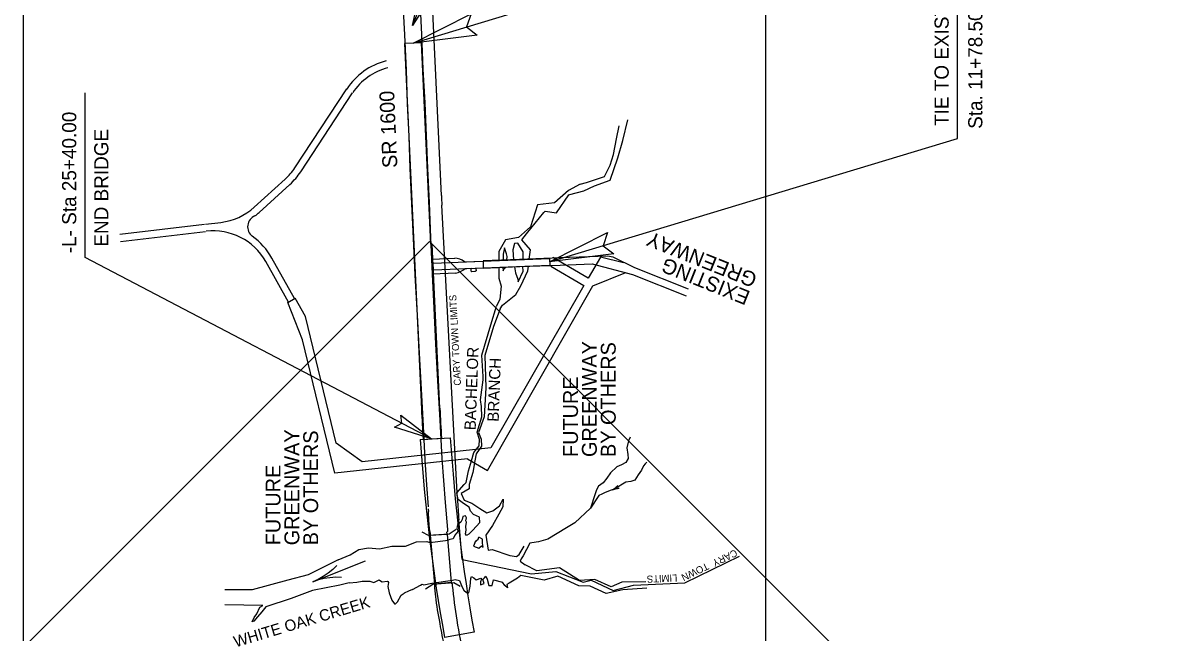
# Model space of a CAD drawing. Extents: x 2026893 to 2039781, y 729195 to 739590.
# Drawn here: x 2028294 to 2029929, y 737234 to 738095 of the extents above; entities that cross this region are included whole.
import ezdxf

# ---------------------------------------------------------------- set-up
doc = ezdxf.new("R2010")
doc.units = 0
for name, color, linetype in [('Default', 7, 'Continuous'), ('Old_Level_1', 7, 'Continuous'), ('Old_Level_11', 7, 'Continuous'), ('Old_Level_2', 7, 'Continuous'), ('Old_Level_20', 7, 'Continuous'), ('Old_Level_22', 7, 'Continuous'), ('Old_Level_3', 7, 'Continuous'), ('Prop Conc 5in Monolithic Keyed In Island', 7, 'Continuous'), ('Prop EOT Dash', 7, 'Continuous'), ('Prop Shade Heavy', 7, 'Continuous'), ('Prop Shade Light', 7, 'Continuous'), ('Prop Terminator CELL', 7, 'Continuous')]:
    doc.layers.add(name, color=color, linetype=linetype)

# ---------------------------------------------------------------- blocks, each defined once
blk = doc.blocks.new('EXIST HYDRO RIVER FLOW ARROW')
at = {"layer": 'Default'}
for p, q in [((0.2, 0), (-0.2, 0)), ((0, 0.04575), (0.03775, 0.03)), ((0, 0), (0, 0)), ((0.03775, 0.03), (0.07725, 0.01725)), ((0.07725, 0.01725), (0.118, 0.00775)), ((0.118, 0.00775), (0.159, 0.0015)), ((0.159, 0.0015), (0.2, 0)), ((0.159, -0.0015), (0.2, 0)), ((0, -0.04575), (0.03775, -0.03)), ((0.03775, -0.03), (0.07725, -0.01725)), ((0.07725, -0.01725), (0.118, -0.00775)), ((0.118, -0.00775), (0.159, -0.0015))]:
    blk.add_line(p, q, dxfattribs=at)
blk = doc.blocks.new('EXIST HYDRO STREAM FLOW ARROW')
at = {"layer": 'Default'}
blk.add_line((0, 0), (0, 0), dxfattribs=at)
for points in [[(-0.1, 0.04575), (-0.07325, 0.03375), (-0.04475, 0.0245), (-0.0165, 0.01575), (0.01175, 0.0095), (0.041, 0.00475), (0.07075, 0.0015), (0.1, 0)], [(-0.1, -0.04575), (-0.07325, -0.03375), (-0.04475, -0.0245), (-0.0165, -0.01575), (0.01175, -0.0095), (0.041, -0.00475), (0.07075, -0.0015), (0.1, 0)]]:
    blk.add_lwpolyline(points, dxfattribs=at)

msp = doc.modelspace()

# ---------------------------------------------------------------- linework, layer by layer
at = {"layer": 'Default'}
for p, q in [((2028885.6, 737851.8), (2028860.8, 738391.3)), ((2028908.3, 737422.7), (2028886.3, 737838.2)), ((2028872.2, 737762.1), (2028904.4, 737763.2)), ((2028915, 737337.3), (2028910.3, 737393.6)), ((2028915, 737337.3), (2029012.9, 737317.4)), ((2029229.7, 737304.3), (2029307, 737342)), ((2029012.9, 737317.4), (2029047.5, 737320.7)), ((2029047.5, 737320.7), (2029086.1, 737305.5)), ((2029086.1, 737305.5), (2029097.3, 737308.2)), ((2029097.3, 737308.2), (2029128.4, 737293.8)), ((2029157.1, 737301.1), (2029229.7, 737304.3)), ((2029128.4, 737293.8), (2029157.1, 737301.1))]:
    msp.add_line(p, q, dxfattribs=at)
for points in [[(2028906, 737742.2), (2028873.2, 737740.5), (2028872.2, 737762.1)], [(2029053.3, 737763.6), (2028995.9, 737761.3), (2028944.6, 737759.3)], [(2029234.7, 737719.4), (2029159.1, 737749.5), (2029128.4, 737764.5), (2029120.6, 737766.3), (2029053.3, 737763.6)], [(2028918.2, 737758.2), (2028944.6, 737759.2), (2028944.9, 737749.3), (2028934.4, 737748.8), (2028934.6, 737745.3), (2028933.6, 737744.3), (2028928.7, 737744.2), (2028927.6, 737745.1), (2028927.5, 737748.6), (2028918.9, 737748.2)], [(2028944.9, 737749.3), (2028996.3, 737751.3), (2029053.3, 737753.6)], [(2029053.3, 737753.6), (2029098.8, 737755.5), (2029155.7, 737740.3), (2029231.5, 737709.9)]]:
    msp.add_lwpolyline(points, dxfattribs=at)
for centre, radius, start, end in [((2030853.6, 737942.3), 1970, 182.6308, 183.0286), ((2029876.9, 737474), 970, 183.0286, 184.7504)]:
    msp.add_arc(centre, radius, start, end, dxfattribs=at)
for centre, major_axis, ratio, start_param, end_param in [((2028904.1, 737740.8), (19.8, 10.5), 0.999895, 0.400767, 1.068838), ((2028899.8, 737772.6), (-23.2, -20.5), 0.998646, 1.047139, 1.510472)]:
    msp.add_ellipse(centre, major_axis=major_axis, ratio=ratio, start_param=start_param, end_param=end_param, dxfattribs=at)
at = {"layer": 'Old_Level_1'}
for p, q in [((2028844.6, 738092.3), (2029101.4, 738704.5)), ((2029615.3, 737932.6), (2029615.3, 738285.3)), ((2028845.7, 738067.3), (2029426.2, 738243.1)), ((2028381.9, 737764.1), (2028381.9, 737996.9)), ((2029038.6, 737758), (2029615.3, 737932.6)), ((2028871.8, 737507.9), (2028381.9, 737764.1))]:
    msp.add_line(p, q, dxfattribs=at)
at = {"layer": 'Old_Level_11'}
for p, q in [((2029142.1, 737929.7), (2029149.1, 737958.6)), ((2029133.2, 737931.8), (2029136.7, 737950.3)), ((2029129, 737910), (2029133.2, 737931.8)), ((2029135, 737905), (2029142.1, 737929.7)), ((2029124.1, 737894.9), (2029129, 737910)), ((2029116.3, 737878.6), (2029124.1, 737894.9)), ((2029124.2, 737873.7), (2029135, 737905)), ((2028972.6, 737750.4), (2028972.9, 737745.3)), ((2029103, 737430.2), (2029096.4, 737410.2))]:
    msp.add_line(p, q, dxfattribs=at)
for points in [[(2029081.7, 737868), (2029090.9, 737870.2), (2029116.3, 737878.6)], [(2029081.7, 737868), (2029065.1, 737859.1), (2029045.3, 737841.5), (2029021.3, 737838.6), (2029011.6, 737807.4), (2028994.6, 737792.7), (2028976.2, 737789.2), (2028966.8, 737772.9), (2028966.7, 737760.2)], [(2029087.1, 737858.6), (2029102, 737865.5), (2029124.2, 737873.7)], [(2029009.9, 737761.9), (2029011.4, 737774.9), (2028999.3, 737789.1), (2029006.1, 737797.6), (2029030.3, 737827.9), (2029032.3, 737829.7), (2029048.4, 737827.6), (2029066, 737852.8), (2029067.1, 737853.4), (2029087.1, 737858.6)], [(2028978.3, 737760.6), (2028978.6, 737765.7), (2028977.5, 737769.5), (2028974.6, 737778.1), (2028972.9, 737769.1), (2028972.9, 737760.4)], [(2029001.1, 737761.5), (2029001.1, 737772.2), (2028993.5, 737784.5), (2028989.2, 737784.1), (2028986.4, 737775.1), (2028987.6, 737761)], [(2028966.7, 737750.1), (2028966.6, 737734.8), (2028970, 737723.6), (2028968.1, 737705.4), (2028963.6, 737695.5)], [(2028968.5, 737691.5), (2028971.9, 737697), (2028990.9, 737711.8), (2028998, 737724.2), (2029008, 737745.3), (2029008.8, 737751.8)], [(2028972.9, 737745.3), (2028974.5, 737748.9), (2028976.5, 737750.5)], [(2028989, 737751), (2028990.5, 737742.4), (2028993.7, 737733.8), (2028994, 737729.9), (2029001, 737744.9), (2029000.9, 737751.5)], [(2028936, 737517.2), (2028942.9, 737539.2), (2028942.1, 737553.6), (2028941, 737562.9), (2028944.5, 737591.2), (2028944.5, 737596.3), (2028943, 737626.4), (2028955.4, 737669.2), (2028963.6, 737695.5)], [(2028968.5, 737691.5), (2028959.1, 737666.6), (2028947.1, 737625.9), (2028948.4, 737580.2), (2028946.1, 737538.9), (2028938.3, 737516.8)], [(2028907.3, 737431.5), (2028917.6, 737443.6), (2028920.6, 737446.1), (2028923.9, 737462.7), (2028928.3, 737476.9), (2028931.5, 737488.6), (2028939.1, 737498), (2028939.7, 737506.9), (2028936, 737517.2)], [(2028938.3, 737516.8), (2028941.8, 737507.5), (2028942.1, 737497.4), (2028934.7, 737486.9), (2028932.9, 737476.7), (2028930, 737460.5), (2028925.1, 737443.5), (2028924.9, 737437.2), (2028913.7, 737430.9), (2028918, 737421.5), (2028928.8, 737417.1), (2028940.1, 737409.4), (2028949.9, 737403.5), (2028958.5, 737406.1), (2028967.8, 737413.4), (2028972.9, 737422.7), (2028972.5, 737411.9), (2028966.7, 737401.3), (2028957.8, 737385.3), (2028948.3, 737371.7), (2028951.6, 737350.7)], [(2029152.3, 737510.2), (2029152.3, 737510.2), (2029149.9, 737505.2), (2029147.8, 737495.3), (2029149.1, 737485.8), (2029149.5, 737480.1), (2029146.3, 737474.3), (2029140, 737471.2), (2029133.4, 737468.4), (2029124.6, 737460), (2029119.5, 737452.2), (2029114.2, 737445.6), (2029107.6, 737440.9), (2029105, 737436.1), (2029103, 737430.2)], [(2029176.2, 737474.9), (2029173.6, 737472.7), (2029171.4, 737469.9), (2029168.5, 737463.8), (2029163.9, 737457.3), (2029159.2, 737449.4), (2029153.5, 737447.8), (2029146.4, 737446.9), (2029139.2, 737442.5), (2029132.3, 737438), (2029124.2, 737434.8), (2029116.2, 737431.8), (2029112.4, 737429.7), (2029108.4, 737428)], [(2028909.2, 737422.1), (2028907.3, 737431.5)], [(2028939.9, 737389.6), (2028939.7, 737397.5), (2028931.1, 737401.1), (2028926.7, 737405.8), (2028925.1, 737411.5), (2028916.9, 737416.7), (2028909.2, 737422.1)], [(2029108.4, 737428), (2029096.4, 737410.2), (2029074.1, 737389.1), (2029062.3, 737382.2)], [(2028939.9, 737389.6), (2028929.9, 737378.7), (2028924.4, 737373.3), (2028921.2, 737371.3), (2028919.9, 737373.5), (2028920.8, 737379.1), (2028920.1, 737384.3), (2028921.3, 737390.3), (2028920, 737392.3), (2028921.2, 737396.3), (2028919.6, 737399.2), (2028915.9, 737398.1), (2028914.8, 737394.1), (2028912.9, 737390), (2028908.6, 737387.1), (2028907.4, 737381.3), (2028909.5, 737377.5), (2028904.6, 737372), (2028902.2, 737366.6), (2028897.4, 737365.9), (2028895.3, 737364.8)], [(2028935.3, 737364.5), (2028937.4, 737366.2), (2028938.7, 737369)], [(2028943.6, 737360.7), (2028943.5, 737366.4), (2028938.7, 737369)], [(2029062.3, 737382.2), (2029035.9, 737366.4), (2029022.7, 737362.5), (2029019.8, 737361.9), (2029010.5, 737360.7), (2029001.1, 737342.8)], [(2028739.8, 737336.9), (2028756.8, 737344.2), (2028768.9, 737351.8), (2028782.7, 737353.9), (2028798, 737352.7), (2028815.5, 737356.1), (2028834.9, 737356.5), (2028850.5, 737362.3), (2028865, 737363.1), (2028869.2, 737361.5), (2028895.3, 737364.8)], [(2028933.1, 737360.8), (2028931.2, 737356.4), (2028938.6, 737353.6), (2028942.1, 737356.6), (2028944.6, 737354.7)], [(2028933.1, 737360.8), (2028935.3, 737364.5)], [(2028944.6, 737354.7), (2028943.6, 737360.7)], [(2028995.4, 737344.6), (2029002.4, 737356.5)], [(2028739.8, 737336.9), (2028697.2, 737316), (2028668.4, 737308.4), (2028618.1, 737294.8), (2028579.3, 737294.5)], [(2028951.6, 737350.7), (2028957.6, 737351.4)], [(2028957.6, 737351.4), (2028982.6, 737343.1), (2028991.6, 737341.8), (2028995.4, 737344.6)], [(2029001.1, 737342.8), (2028998.6, 737338.6), (2028997.1, 737335.1), (2029004.1, 737329.9)], [(2029020.4, 737321.3), (2029004.1, 737329.9)], [(2029174.4, 737306.1), (2029140.9, 737305.3), (2029125.5, 737298.6), (2029102.5, 737309.4), (2029081, 737307.8), (2029052.4, 737325.7), (2029020.4, 737321.3)], [(2028755.1, 737304.3), (2028742, 737301.2), (2028703.6, 737293.8), (2028673.4, 737282.3), (2028637.6, 737270.6), (2028631.7, 737263.7), (2028625.5, 737256.2), (2028620.6, 737250.4), (2028618, 737249.4), (2028621.2, 737255.7), (2028624.7, 737260.6), (2028628.9, 737270.2), (2028633.3, 737272.3), (2028579.6, 737273.2)], [(2028755.1, 737304.3), (2028766.3, 737305.4), (2028773.5, 737307), (2028784.3, 737306.8), (2028790.1, 737304.9), (2028797.6, 737308.9), (2028799.7, 737307.5), (2028802, 737306.1), (2028808.8, 737306.7), (2028810.1, 737306.4), (2028810.8, 737305.1), (2028809.8, 737299.5), (2028811.7, 737290.4)], [(2028845, 737295), (2028856.1, 737301.2), (2028858.4, 737302.4), (2028860.8, 737301.8), (2028872, 737304.2), (2028901.1, 737308.2)], [(2028901.1, 737308.2), (2028905.1, 737309.1), (2028911.1, 737307.6), (2028914.9, 737298.4), (2028917.5, 737293.9), (2028920.9, 737290.8), (2028924.5, 737290.3), (2028926.2, 737299.9), (2028927.2, 737310.7), (2028928, 737313.2), (2028931.3, 737311.5), (2028934.7, 737308.7), (2028941.3, 737311.1), (2028942.4, 737309.5), (2028941, 737306), (2028941, 737301.5), (2028945.9, 737303.5), (2028944.3, 737309.4), (2028946.7, 737311.7), (2028948.6, 737314)], [(2028948.6, 737314), (2028950.5, 737309.5)], [(2028950.5, 737309.5), (2028952.9, 737300.7), (2028956.9, 737300.7), (2028957.4, 737300.9), (2028959.2, 737308.9), (2028972.1, 737305.2)], [(2028993.1, 737311.1), (2028981.5, 737304.2), (2028977.9, 737302), (2028979, 737297.5), (2028975.3, 737300.7), (2028972.1, 737305.2)], [(2028997.7, 737314.7), (2028993.1, 737311.1)], [(2029175.8, 737297), (2029142, 737294.5), (2029118.7, 737289.3), (2029095.9, 737299.8), (2029079.8, 737300), (2029050.1, 737314), (2029031, 737308), (2028997.7, 737314.7)], [(2028811.7, 737290.4), (2028815.7, 737279.9), (2028819.2, 737274.9), (2028820.7, 737275), (2028823.6, 737277.7), (2028828.6, 737287.1), (2028832.8, 737289.9)], [(2028845, 737295), (2028839, 737292.5), (2028832.8, 737289.9)]]:
    msp.add_lwpolyline(points, dxfattribs=at)
at = {"layer": 'Old_Level_20'}
for p, q in [((2028868.8, 737786.8), (2028294.4, 737212.4)), ((2029344.4, 737311.2), (2028868.8, 737786.8))]:
    msp.add_line(p, q, dxfattribs=at)
at = {"layer": 'Old_Level_22'}
for p, q in [((2028294.4, 738629.8), (2028294.4, 737129.7)), ((2029344.4, 737129.7), (2029344.4, 738629.7)), ((2028857.7, 738067.8), (2028833.7, 738066.7)), ((2028833.7, 738066.7), (2028857.5, 737549.9)), ((2028870.8, 737783.1), (2028857.7, 738067.8)), ((2028872.8, 737783.2), (2028870.8, 737783.1)), ((2028883.4, 737551.1), (2028872.8, 737783.2)), ((2028859.8, 737507.1), (2028885.8, 737508.8)), ((2029929.5, 736726.1), (2029344.4, 737311.2))]:
    msp.add_line(p, q, dxfattribs=at)
for radius in [2412, 2386]:
    msp.add_arc((2031266.9, 737660.6), radius, 182.6308, 183.6478, dxfattribs=at)
at = {"layer": 'Old_Level_3'}
msp.add_line((2028867, 737409), (2028867.2, 737405.4), dxfattribs=at)
for points in [[(2028891.4, 737417.9), (2028886.9, 737480.2), (2028883.8, 737534.3), (2028880.8, 737589.8), (2028877.9, 737642.4), (2028875.3, 737692.7), (2028873, 737740.5), (2028870.7, 737792.7), (2028868.6, 737841.5), (2028866.5, 737889.9), (2028862.6, 737982.7), (2028860.1, 738030.3), (2028858, 738079.6), (2028855.7, 738128.3), (2028853.7, 738176), (2028851, 738227.2), (2028849, 738276.4), (2028846.7, 738325.3), (2028845.4, 738355.3)], [(2028819.7, 738339.7), (2028823.3, 738286.5), (2028825.8, 738237.2), (2028828.4, 738187.7), (2028830.3, 738140.3), (2028833.4, 738078.8), (2028835.7, 738029.1), (2028837.3, 737981.2), (2028839.4, 737935.7), (2028841.2, 737889.8), (2028843.4, 737840.1), (2028845.7, 737790.9), (2028848.1, 737739.3), (2028851.5, 737682.8), (2028854.1, 737628.7), (2028856.9, 737578.1), (2028859.8, 737526), (2028862.4, 737478.4), (2028864.4, 737442.8), (2028866.7, 737411.7)], [(2028893.7, 737373.9), (2028893.5, 737375.9), (2028894.7, 737377.3), (2028894.7, 737379.9), (2028891.4, 737417.9)], [(2028858.1, 737376.5), (2028867.1, 737371.9), (2028896.8, 737373.7), (2028906.7, 737380.1)], [(2028868.3, 737383.5), (2028868.4, 737380.7), (2028869.8, 737374), (2028869.9, 737372.5)], [(2028869.9, 737371.9), (2028893.9, 737373.4), (2028899.6, 737305), (2028875.7, 737302.7)], [(2028869.9, 737371.9), (2028875.7, 737302.7)], [(2028863.2, 737296.1), (2028873.4, 737302.6), (2028903, 737305), (2028912.3, 737299.7)], [(2028901.5, 737300.9), (2028901.4, 737302.9), (2028899.9, 737303.4), (2028899.8, 737304.5)], [(2028875.9, 737302.5), (2028876, 737297.4)]]:
    msp.add_lwpolyline(points, dxfattribs=at)
msp.add_ellipse((2028579.1, 737379.7), major_axis=(-9.9, 295.3), ratio=0.97889, start_param=4.692284, end_param=4.766746, dxfattribs=at)
for points in [[(2028876, 737297.4), (2028877.7, 737280.7), (2028884.1, 737242.4), (2028890.4, 737209.5), (2028897.8, 737176.1), (2028905.3, 737145.9), (2028914.1, 737113.4), (2028927.8, 737062.5), (2028942.5, 737009), (2028956.7, 736958.8), (2028970.6, 736908.1), (2028981.4, 736866.4), (2028994.6, 736816.4), (2029007.2, 736768.1), (2029020.4, 736717.4), (2029030.8, 736675.2)], [(2028959.3, 737040.6), (2028944.8, 737094.7), (2028931, 737147.5), (2028918.6, 737198.8), (2028907.8, 737251.5), (2028901.5, 737300.9)]]:
    msp.add_spline(points, degree=3, dxfattribs=at)
at = {"layer": 'Prop Conc 5in Monolithic Keyed In Island'}
msp.add_lwpolyline([(2028874.4, 737746.3), (2028874, 737756.3), (2029038.4, 737763), (2029038.8, 737753)], close=True, dxfattribs=at)
at = {"layer": 'Prop EOT Dash'}
for p, q in [((2029093.1, 737735.1), (2029043.3, 737764.2)), ((2029110.5, 737764.9), (2029093.1, 737735.1)), ((2029143, 737756.5), (2029110.5, 737764.9)), ((2029040.2, 737752), (2029087, 737724.7)), ((2029099.9, 737724), (2029146.2, 737743)), ((2028951, 737463.2), (2029099.9, 737724)), ((2029087, 737724.7), (2028955.4, 737495.2)), ((2028668.6, 737700.8), (2028679.1, 737706.6)), ((2028689.3, 737647.8), (2028668.6, 737700.8)), ((2028693.6, 737680.9), (2028679.1, 737706.6)), ((2028736.9, 737501.7), (2028693.6, 737680.9)), ((2028734.8, 737459.3), (2028689.3, 737647.8)), ((2028773.8, 737475.6), (2028736.9, 737501.7)), ((2028955.4, 737495.2), (2028773.8, 737475.6)), ((2028922.3, 737479.6), (2028734.8, 737459.3)), ((2028922.3, 737479.6), (2028951, 737463.2))]:
    msp.add_line(p, q, dxfattribs=at)
for points in [[(2028678.5, 737891), (2028751.9, 738002.4)], [(2028686.8, 737885.5), (2028760.2, 737996.9)], [(2028621.2, 737835.4), (2028664.7, 737874.9)], [(2028627.9, 737828), (2028671.4, 737867.5)], [(2028430.9, 737797), (2028551, 737811.2)], [(2028552, 737811.3), (2028574, 737813.9)], [(2028432.1, 737787), (2028552.2, 737801.2)], [(2028678.2, 737706.2), (2028646, 737763.5)], [(2028669.5, 737701.3), (2028637.3, 737758.6)]]:
    msp.add_lwpolyline(points, dxfattribs=at)
for centre, radius, start, end in [((2028831.2, 737950.1), 95, 104.526, 146.6179), ((2028831.2, 737950.1), 85, 104.526, 146.6179), ((2028607.5, 737937.8), 85, 312.2527, 326.6179), ((2028607.5, 737937.8), 95, 312.2527, 326.6179), ((2028564, 737898.3), 85, 276.74, 312.2527), ((2028564, 737898.3), 95, 307.6996, 312.2527), ((2028628.5, 737807.6), 16.8, 112.2241, 232.4804), ((2028563.2, 737716.9), 85, 29.3209, 96.74), ((2028563.2, 737716.9), 95, 29.3209, 54.5571)]:
    msp.add_arc(centre, radius, start, end, dxfattribs=at)
at = {"layer": 'Prop Shade Heavy'}
for p, q in [((2028855.8, 737506.9), (2028898.2, 737509.6)), ((2028931.9, 737234.9), (2028890.1, 737227.3))]:
    msp.add_line(p, q, dxfattribs=at)
for radius in [2416, 2373.5]:
    msp.add_arc((2031266.9, 737660.6), radius, 183.6478, 190.3323, dxfattribs=at)
at = {"layer": 'Prop Shade Light'}
for p, q in [((2028857.7, 738067.8), (2028833.7, 738066.7)), ((2028833.7, 738066.7), (2028857.5, 737549.9)), ((2028870.8, 737783.1), (2028857.7, 738067.8)), ((2028872.8, 737783.2), (2028870.8, 737783.1)), ((2028883.4, 737551.1), (2028872.8, 737783.2)), ((2028859.8, 737507.1), (2028885.8, 737508.8))]:
    msp.add_line(p, q, dxfattribs=at)
for radius in [2412, 2386]:
    msp.add_arc((2031266.9, 737660.6), radius, 182.6308, 183.6478, dxfattribs=at)
at = {"layer": 'Prop Terminator CELL'}
for points in [[(2028874, 738138.5), (2028844.6, 738092.3), (2028856.7, 738146), (2028862.9, 738136)], [(2028936.3, 738078.5), (2028845.7, 738067.3), (2028927.7, 738108.8), (2028921.3, 738090.2)], [(2029129.2, 737769.2), (2029038.6, 737758), (2029120.6, 737799.5), (2029114.2, 737780.9)], [(2028828.2, 737541.2), (2028871.8, 737507.9), (2028819.2, 737524.5), (2028829.8, 737529.9)]]:
    msp.add_lwpolyline(points, close=True, dxfattribs=at)

# ---------------------------------------------------------------- block references
at = {"layer": 'Old_Level_11'}
for name, p, xscale, yscale, rotation in [('EXIST HYDRO STREAM FLOW ARROW', (2029131.4, 737437.6), 50.00000000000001, 49.99999999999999, -153.81210117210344), ('EXIST HYDRO RIVER FLOW ARROW', (2028741.2, 737320.7), 199.99999999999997, 200.00000000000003, -158.00794512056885), ('EXIST HYDRO RIVER FLOW ARROW', (2028741.2, 737320.7), 199.99999999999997, 200.00000000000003, -158.00794512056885)]:
    msp.add_blockref(name, p, dxfattribs=dict(at, xscale=xscale, yscale=yscale, rotation=rotation))

# ---------------------------------------------------------------- texts
at = {"layer": 'Default'}
for s, rotation, p in [('CARY TOWN LIMITS', 93.0286, (2028913.4, 737583.4)), ('CARY', 205.9633, (2029300.9, 737352.2)), ('TOWN', 205.9633, (2029260.4, 737333.3)), ('LIMITS', 182.5217, (2029218.9, 737316.4))]:
    msp.add_text(s, height=10, rotation=rotation, dxfattribs=at).set_placement(p)
at = {"layer": 'Old_Level_1'}
for s, p in [('TIE TO EXIST.   BOARDWALK', (2029602.7, 737950.2)), ('Sta. 11+78.50 -GRNWY-', (2029650.3, 737946.1)), ('-L- Sta 25+40.00', (2028369.5, 737770.3)), ('END BRIDGE', (2028414.9, 737779.6))]:
    msp.add_text(s, height=20, rotation=90, dxfattribs=at).set_placement(p)
at = {"layer": 'Old_Level_11'}
for s, rotation, p in [('BACHELOR', 87.9571, (2028934.1, 737520)), ('BRANCH', 87.9571, (2028966.6, 737531.9)), ('WHITE OAK CREEK', 16.6525, (2028594.8, 737213.1))]:
    msp.add_text(s, height=16, rotation=rotation, dxfattribs=at).set_placement(p)
at = {"layer": 'Old_Level_2'}
for s, rotation, p in [('SR 1600', 92.4896, (2028823.5, 737891.2)), ('GREENWAY', 158.1739, (2029333.6, 737740.6)), ('EXISTING', 158.1739, (2029323.7, 737715.9)), ('GREENWAY', 90, (2029105.3, 737482.3)), ('BY OTHERS', 90, (2029132, 737482.3)), ('FUTURE', 90, (2029078.7, 737482.3)), ('GREENWAY', 90, (2028684.8, 737357.5)), ('BY OTHERS', 90, (2028711.4, 737357.5)), ('FUTURE', 90, (2028658.2, 737357.5))]:
    msp.add_text(s, height=21, rotation=rotation, dxfattribs=at).set_placement(p)

doc.saveas('drawing.dxf')
